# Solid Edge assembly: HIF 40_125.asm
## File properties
Title: Zylinder
Author: ahadarics
Template: iso assembly.asm
Last saved by: ahadarics
Revision: 35
Application: Solid Edge
Username: ahadarics
Dokumentum tartalom típus: 1
Document Number: HIF 40/125
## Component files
Kit_2.par
Kit_1.par
Profilrohr 40_125.par
Mutter.par
Kolbenstange 40_125.par
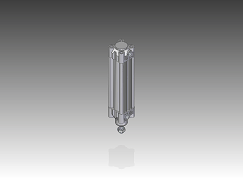
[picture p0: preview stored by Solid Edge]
